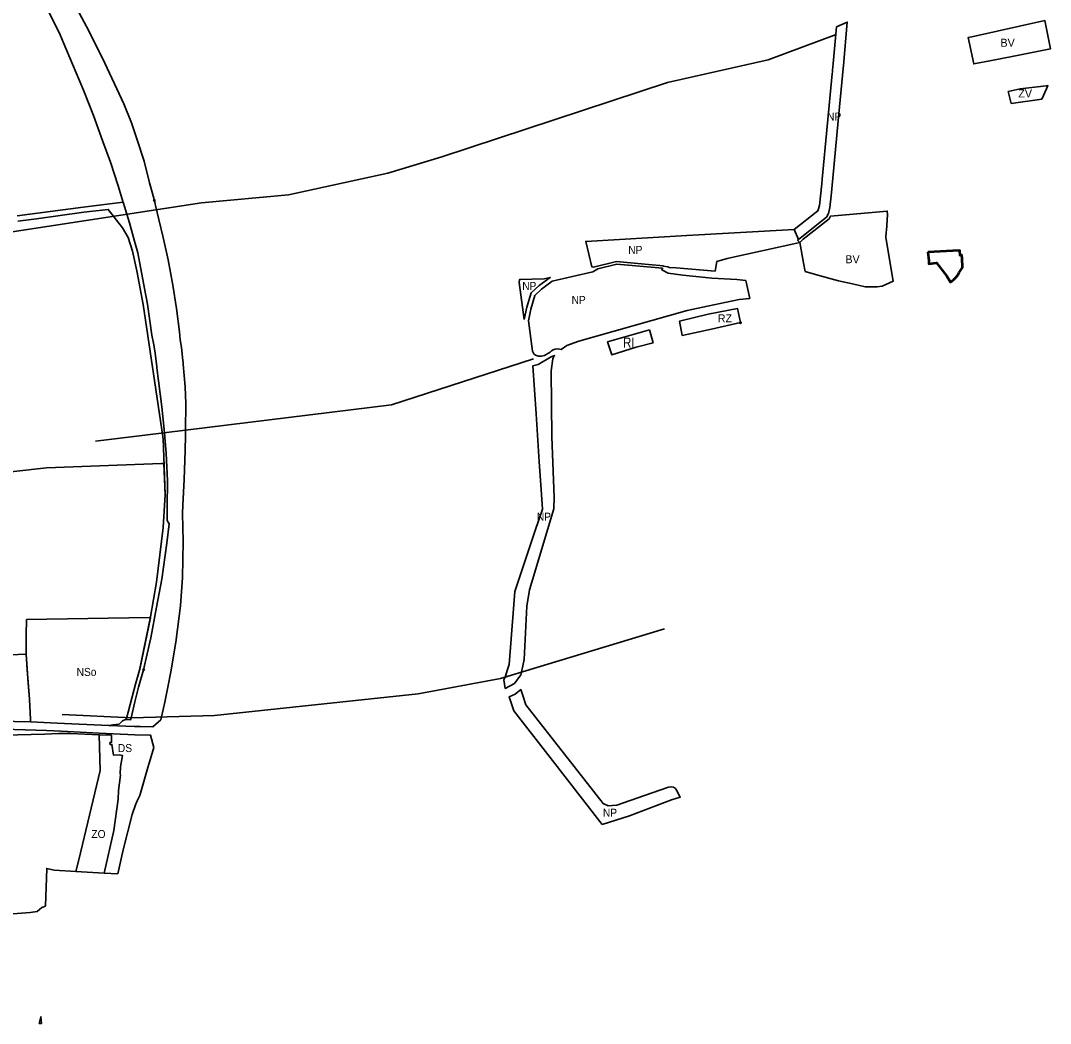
# Model space of a CAD drawing. Extents: x -650276 to -642489, y -1074311 to -1066658.
# Drawn here: x -645218 to -643674, y -1071205 to -1069701 of the extents above; entities that cross this region are included whole.
import ezdxf

# ---------------------------------------------------------------- set-up
doc = ezdxf.new("R2010")
doc.units = 0
doc.header["$LTSCALE"] = 4.8
doc.header["$PDMODE"] = 32
doc.header["$PDSIZE"] = 2.4
for name, color, linetype, lineweight in [('15', 7, 'Continuous', 35), ('24', 7, 'Continuous', 35), ('3', 7, 'Continuous', 35), ('40', 7, 'Continuous', 35), ('42', 7, 'Continuous', 35), ('46', 7, 'Continuous', 35), ('48', 7, 'Continuous', 35), ('54', 7, 'Continuous', 35), ('56', 7, 'Continuous', 35), ('6', 7, 'Continuous', 35), ('60', 7, 'Continuous', 53), ('8', 7, 'Continuous', 35)]:
    doc.layers.add(name, color=color, linetype=linetype, lineweight=lineweight)
doc.layers.add('62', color=7, linetype='Continuous')
doc.layers.add('63', color=7, linetype='Continuous')

msp = doc.modelspace()

# ---------------------------------------------------------------- linework, layer by layer
at = {"layer": '15'}
for points in [[(-645061.76, -1069981.21), (-645064.052, -1069973.429), (-645124.233, -1069980.695), (-645222.809, -1069993.701)], [(-645033.53, -1070674.55), (-645022.64, -1070626.93), (-645014.07, -1070580.72), (-645006.44, -1070538.78), (-644998.92, -1070484.58), (-644995.14, -1070455.72), (-644998.17, -1070450.59), (-644998.25, -1070430.5), (-644997.87, -1070391.16), (-644999.47, -1070349.63), (-645001.64, -1070326.4), (-645001.81, -1070324.58), (-645002.308, -1070319.268), (-645005.98, -1070280.14), (-645013.51, -1070222.04), (-645013.77, -1070220.04), (-645016.92, -1070196.32), (-645018.56, -1070184.92), (-645021.14, -1070173.07), (-645027.49, -1070126.56), (-645032.21, -1070102.73), (-645042.27, -1070049.23), (-645047.28, -1070031.83), (-645054.73, -1070004.56), (-645060.612, -1069985.022), (-645061.76, -1069981.21)], [(-645221.99, -1070001.66), (-645194.003, -1069998.417), (-645123.206, -1069988.629), (-645086.484, -1069984.195), (-645065.235, -1070011.695)], [(-645065.235, -1070011.695), (-645056.555, -1070026.163), (-645050.293, -1070047.035), (-645043.92, -1070076.344), (-645034.122, -1070126.616), (-645004.791, -1070324.889), (-645004.523, -1070326.697)], [(-645004.523, -1070326.697), (-645004.434, -1070327.302), (-645001.312, -1070412.099), (-645004.327, -1070461.264), (-645014.277, -1070543.11), (-645023.048, -1070595.033), (-645039.574, -1070675.065)], [(-645039.574, -1070675.065), (-645045.493, -1070696.321), (-645059.308, -1070747.712), (-645059.403, -1070749.195), (-645053.21, -1070749.75), (-645052.4, -1070746.427), (-645046.63, -1070722.77), (-645041, -1070700.44), (-645033.53, -1070674.55)]]:
    msp.add_lwpolyline(points, dxfattribs=at)
msp.add_point((-645033.53, -1070674.55), dxfattribs=at)
at = {"layer": '24'}
msp.add_line((-645071.18, -1070855.63), (-645071.77, -1070868.73), dxfattribs=at)
for points in [[(-645322.13, -1069447.96), (-645309.62, -1069467.79), (-645303.57, -1069480.49), (-645268.57, -1069533.23), (-645242.75, -1069570.26), (-645230.42, -1069597.39), (-645227.27, -1069602.68), (-645225.7, -1069605.32), (-645214.76, -1069622.37), (-645198.41, -1069650.49), (-645185.17, -1069673.38), (-645179.12, -1069681.3), (-645170.3, -1069698.91), (-645158.43, -1069722.61), (-645153.44, -1069734.71), (-645140.27, -1069766.68), (-645123.84, -1069805.38), (-645108.74, -1069843.58), (-645094.42, -1069882.65), (-645083.31, -1069913.37), (-645071.53, -1069948.89), (-645063.96, -1069973.73), (-645063.23, -1069976.2), (-645062.57, -1069978.46)], [(-645017.46, -1069970.61), (-645018.28, -1069967.49), (-645024.45, -1069944.43), (-645032.85, -1069912.07), (-645043.5, -1069878.37), (-645051.78, -1069854.2), (-645063.26, -1069825.99), (-645095.1, -1069757.62), (-645118.98, -1069710.08), (-645143.56, -1069664.05), (-645148.8, -1069656.1), (-645150.3, -1069653.84), (-645153.33, -1069649.24), (-645166.67, -1069629), (-645184.88, -1069596.58), (-645202.56, -1069568.23), (-645230.1, -1069525.98)], [(-645062.57, -1069978.46), (-645061.76, -1069981.21), (-645060.612, -1069985.022), (-645054.73, -1070004.56), (-645047.28, -1070031.83), (-645042.27, -1070049.23), (-645032.21, -1070102.73), (-645027.49, -1070126.56), (-645021.14, -1070173.07), (-645018.56, -1070184.92), (-645016.92, -1070196.32), (-645013.77, -1070220.04), (-645013.51, -1070222.04), (-645005.98, -1070280.14), (-645002.308, -1070319.268), (-645001.81, -1070324.58), (-645001.64, -1070326.4), (-644999.47, -1070349.63), (-644997.87, -1070391.16), (-644998.25, -1070430.5), (-644998.17, -1070450.59), (-644995.14, -1070455.72), (-644998.92, -1070484.58), (-645006.44, -1070538.78), (-645014.07, -1070580.72), (-645022.64, -1070626.93), (-645033.53, -1070674.55)], [(-644996.88, -1070059.73), (-645004.02, -1070026.44), (-645010.54, -1069999.3), (-645015.548, -1069978.177), (-645016.01, -1069976.23), (-645016.89, -1069972.82), (-645017.46, -1069970.61)], [(-645033.53, -1070674.55), (-645041, -1070700.44), (-645046.63, -1070722.77), (-645052.4, -1070746.427), (-645053.21, -1070749.75), (-645060.46, -1070749.1), (-645065.17, -1070751.39), (-645070.3, -1070755.92), (-645079.38, -1070756.91), (-645085.58, -1070758.04), (-645047.39, -1070759.71), (-645038.44, -1070759.83), (-645019.57, -1070760.07), (-645007.68, -1070749.5), (-645006.739, -1070745.384), (-645001.71, -1070723.39), (-644997.14, -1070700.88), (-644992.6, -1070677.92), (-644985.04, -1070633.43), (-644978.44, -1070578.56), (-644975.05, -1070536.16), (-644974.44, -1070482.48), (-644975.29, -1070440.14), (-644974.69, -1070427.86), (-644972.48, -1070389.15), (-644971.37, -1070345.98), (-644970.61, -1070323.44), (-644970.55, -1070321.56), (-644970.524, -1070315.358), (-644970.36, -1070275.49), (-644971.47, -1070250.14), (-644974, -1070216.2), (-644974.29, -1070213.17), (-644974.49, -1070210.98), (-644976.94, -1070191.41), (-644978.49, -1070180.05), (-644979.57, -1070167.9), (-644984.21, -1070132.81), (-644989.62, -1070097.79), (-644996.88, -1070059.73)], [(-645303, -1070774), (-645182, -1070771), (-645161, -1070770)], [(-645071.99, -1070980.72), (-645064.39, -1070944.7), (-645050.47, -1070891.48), (-645045.74, -1070877.19), (-645043, -1070871.35), (-645039.25, -1070863.33), (-645028.25, -1070824.83), (-645018.18, -1070791.34), (-645023.25, -1070772.62), (-645046.46, -1070771.98), (-645100.32, -1070769.5), (-645156.988, -1070766.884), (-645179.18, -1070765.86), (-645275.8, -1070762.66)], [(-645161, -1070770), (-645143, -1070770), (-645100.268, -1070771.946)], [(-645100.268, -1070771.946), (-645081.75, -1070772.79), (-645081.85, -1070781.59), (-645081.57, -1070783.53)], [(-645081.57, -1070783.53), (-645083.95, -1070783.89), (-645083.49, -1070786.92), (-645081.13, -1070786.56), (-645078.85, -1070802.46), (-645070.2, -1070802.33)], [(-645070.2, -1070802.33), (-645065.01, -1070803.22), (-645068.07, -1070820.37)], [(-645068.07, -1070820.37), (-645068.52, -1070830.52), (-645068.07, -1070832.72), (-645071.18, -1070855.63)], [(-645071.77, -1070868.73), (-645078.23, -1070915.65), (-645092.67, -1070979.52), (-645071.99, -1070980.72)]]:
    msp.add_lwpolyline(points, dxfattribs=at)
for p in [(-645017.46, -1069970.61), (-645033.53, -1070674.55)]:
    msp.add_point(p, dxfattribs=at)
at = {"layer": '3'}
for points in [[(-643791.88, -1069725.25), (-643797.75, -1069726.51), (-643789.3, -1069766.05), (-643786.35, -1069765.46), (-643764.94, -1069761.27), (-643729.34, -1069754.3), (-643674.3, -1069743.53), (-643682.61, -1069701.16)], [(-643920.84, -1070026.46), (-643920.29, -1070017.73), (-643920.16, -1070015.69), (-643918.69, -1069992.23), (-643918.88, -1069986.82), (-644004.06, -1069994.59), (-644005.92, -1069998.62), (-644044.7, -1070029.04), (-644050.12, -1070033.64), (-644044.18, -1070064.43), (-644041.71, -1070077.29), (-644022.77, -1070082.66), (-643991.99, -1070091.37), (-643971.03, -1070095.79), (-643951.99, -1070100.35), (-643933.96, -1070100.18), (-643926.33, -1070099.5), (-643909.87, -1070091.95)]]:
    msp.add_lwpolyline(points, close=True, dxfattribs=at)
at = {"layer": '40'}
for points in [[(-643737.47, -1069807.24), (-643733.02, -1069825.4), (-643687.2, -1069818.8), (-643680.15, -1069803.22), (-643678.02, -1069798.52), (-643680.83, -1069798.86), (-643719.42, -1069803.49)], [(-645442.836, -1070659.455), (-645426.34, -1070660.33), (-645209.41, -1070651.2), (-645206.7, -1070694.76), (-645204.66, -1070718.51), (-645203.13, -1070749.36), (-645202.96, -1070752.89), (-645275.236, -1070750.954), (-645282, -1070742), (-645301, -1070736), (-645324, -1070736), (-645379, -1070743), (-645415, -1070737), (-645435.711, -1070727.497)]]:
    msp.add_lwpolyline(points, close=True, dxfattribs=at)
at = {"layer": '42'}
for points in [[(-645100.268, -1070771.946), (-645098.438, -1070825.558), (-645130.749, -1070959.561), (-645134.972, -1070977.077)], [(-645081.85, -1070781.59), (-645081.75, -1070772.79), (-645100.268, -1070771.946), (-645098.438, -1070825.558), (-645130.749, -1070959.561)], [(-645092.67, -1070979.52), (-645078.23, -1070915.65), (-645071.77, -1070868.73), (-645071.18, -1070855.63), (-645068.07, -1070832.72), (-645068.52, -1070830.52), (-645068.07, -1070820.37), (-645065.01, -1070803.22), (-645070.2, -1070802.33), (-645078.85, -1070802.46), (-645081.13, -1070786.56), (-645081.13, -1070786.56), (-645083.49, -1070786.92), (-645083.95, -1070783.89), (-645081.57, -1070783.53), (-645081.85, -1070781.59), (-645081.75, -1070772.79), (-645100.268, -1070771.946)], [(-645092.67, -1070979.52), (-645078.23, -1070915.65), (-645071.77, -1070868.73), (-645071.18, -1070855.63), (-645068.07, -1070832.72), (-645068.52, -1070830.52), (-645068.07, -1070820.37), (-645065.01, -1070803.22), (-645070.2, -1070802.33), (-645078.85, -1070802.46), (-645081.13, -1070786.56), (-645083.49, -1070786.92)], [(-645083.49, -1070786.92), (-645083.95, -1070783.89), (-645081.57, -1070783.53), (-645081.85, -1070781.59)], [(-645130.749, -1070959.561), (-645134.972, -1070977.077), (-645092.67, -1070979.52)]]:
    msp.add_lwpolyline(points, dxfattribs=at)
msp.add_lwpolyline([(-645186.64, -1071204.86), (-645187.466, -1071194.782), (-645189.902, -1071204.885)], close=True, dxfattribs=at)
msp.add_lwpolyline([(-645186.64, -1071204.86), (-645187.466, -1071194.782), (-645189.902, -1071204.885)], close=True, dxfattribs=at)
at = {"layer": '46'}
for points in [[(-645023.048, -1070595.033), (-645014.277, -1070543.11), (-645004.327, -1070461.264), (-645001.312, -1070412.099), (-645003.03, -1070365.427), (-645003.102, -1070365.432), (-645006.86, -1070365.38), (-645179.26, -1070371.74), (-645326.62, -1070388.32), (-645414.65, -1070395.37), (-645409.38, -1070411.41), (-645408.66, -1070414.62), (-645404.34, -1070433.93), (-645404.4, -1070435.88), (-645440.61, -1070469.53), (-645451.226, -1070466.394), (-645455.09, -1070479.21), (-645458.46, -1070478.86), (-645454.02, -1070501.52), (-645448.36, -1070563), (-645449.82, -1070592.72), (-645442.834, -1070659.455)], [(-645209.41, -1070651.2), (-645209.79, -1070622.69), (-645208.96, -1070599.22)], [(-645208.96, -1070599.22), (-645025.12, -1070596.42), (-645023.346, -1070596.478), (-645023.048, -1070595.033)], [(-645442.834, -1070659.455), (-645426.34, -1070660.33), (-645209.41, -1070651.2)]]:
    msp.add_lwpolyline(points, dxfattribs=at)
at = {"layer": '48'}
for points in [[(-643995.17, -1069710.42), (-643999.94, -1069765.62), (-644000.79, -1069775.42), (-644001.04, -1069778.063), (-644001.29, -1069780.7), (-644016.47, -1069938.99), (-644017.15, -1069945.93), (-644020.26, -1069978.38), (-644022.43, -1069984.87), (-644022.99, -1069986.58), (-644058.55, -1070014.4), (-644051.913, -1070029.549), (-644049.311, -1070027.453), (-644009.95, -1069995.74), (-644006.96, -1069990.34), (-644005.06, -1069981.28), (-644003.06, -1069964.06), (-644000.52, -1069937.19), (-643992.27, -1069851.31), (-643984.845, -1069772.863), (-643984.44, -1069768.58), (-643978.85, -1069703.4), (-643986.744, -1069706.796)], [(-644381.21, -1070181.71), (-644218.65, -1070135.75), (-644188.44, -1070129.43), (-644140.72, -1070119.57), (-644125, -1070117.83), (-644130.91, -1070091.1), (-644144.13, -1070089.47), (-644181.81, -1070087.51), (-644191.26, -1070086.47), (-644225.13, -1070082.95), (-644247.3, -1070079.69), (-644256.54, -1070075.02), (-644255.52, -1070072.5), (-644324.42, -1070066.48), (-644352.71, -1070073.46), (-644360.41, -1070077.91), (-644421.26, -1070091.99), (-644437.34, -1070103.76), (-644447.13, -1070113.11), (-644453.22, -1070133.99), (-644456.41, -1070151.18), (-644450.72, -1070196.97), (-644448.76, -1070200.77), (-644445.9, -1070202.83), (-644441.8, -1070204.26), (-644437.415, -1070204.436), (-644432.53, -1070203.32), (-644424.14, -1070198.29), (-644421.88, -1070196.28), (-644419.51, -1070194.76), (-644416.67, -1070193.7), (-644412.54, -1070193.18), (-644407.55, -1070194.16), (-644399.15, -1070188.55)], [(-644463.28, -1070149.42), (-644459.09, -1070131.08), (-644452.65, -1070109.46), (-644440.64, -1070098.4), (-644423.99, -1070086.17), (-644433.19, -1070088.37), (-644470.17, -1070089.43), (-644470.55, -1070093.61)], [(-644491.691, -1070685.524), (-644491.82, -1070685.92), (-644493.5, -1070689.75), (-644491.42, -1070702.64), (-644477.46, -1070695.09), (-644467.84, -1070682.37), (-644466.998, -1070678.065), (-644463.28, -1070659.06), (-644458.85, -1070579.04), (-644455.2, -1070554.88), (-644418.69, -1070433.36), (-644418.23, -1070415.62), (-644421.45, -1070325.29), (-644422.5, -1070226.42), (-644420.14, -1070208.56), (-644418.61, -1070204.51), (-644417.36, -1070203.24), (-644421.47, -1070204.77), (-644423.66, -1070205.86), (-644442.2, -1070216.72), (-644450.15, -1070219.06), (-644445.28, -1070290.84), (-644440.36, -1070362.62), (-644437.53, -1070404.1), (-644435.51, -1070433.85), (-644447.14, -1070467.28), (-644460.5, -1070507.68), (-644464.98, -1070521.13), (-644476.94, -1070557.45), (-644479.06, -1070583.13), (-644485.64, -1070666.7), (-644488.01, -1070674.2)], [(-644346.21, -1070906.61), (-644305.07, -1070893.39), (-644242.29, -1070869.82), (-644229.12, -1070865.52), (-644234.66, -1070855.08), (-644236.3, -1070852.87), (-644239.47, -1070850.71), (-644243.15, -1070849.89), (-644246.93, -1070850.52), (-644282.77, -1070863.19), (-644324.34, -1070877.71), (-644337.15, -1070878.64), (-644344.86, -1070875.09), (-644460.82, -1070727.21), (-644465.31, -1070713.25), (-644468.1, -1070704.23), (-644476.35, -1070710.99), (-644485.61, -1070714.95), (-644478.67, -1070736.28), (-644424.37, -1070806.03)]]:
    msp.add_lwpolyline(points, close=True, dxfattribs=at)
for points in [[(-644058.55, -1070014.4), (-644219.33, -1070023.53), (-644370.87, -1070032.13), (-644361.74, -1070070.32), (-644359.02, -1070070.67), (-644324.72, -1070062.44), (-644276.85, -1070066.62), (-644254.13, -1070069.08)], [(-644177.01, -1070076.69), (-644177.01, -1070076.69), (-644174.12, -1070062.16), (-644159.02, -1070057.84), (-644050.12, -1070033.64), (-644053.18, -1070030.57), (-644051.913, -1070029.549), (-644058.55, -1070014.4)], [(-644254.13, -1070069.08), (-644254.25, -1070069.37), (-644247.72, -1070070.21), (-644245.9, -1070071.26), (-644235.49, -1070072.08), (-644177.01, -1070076.69)]]:
    msp.add_lwpolyline(points, dxfattribs=at)
at = {"layer": '54'}
for points in [[(-645230.538, -1070017.864), (-644946.741, -1069974.541), (-644816.387, -1069962.572), (-644667.646, -1069930.034), (-644586.303, -1069905.244), (-644248.286, -1069794.155), (-644097.378, -1069760.147), (-643995.653, -1069721.915)], [(-645105.781, -1070331.996), (-645031.648, -1070322.877), (-644662.188, -1070277.428), (-644449.34, -1070208.499)], [(-645155.795, -1070741.501), (-645051.039, -1070746.492), (-644927.167, -1070743.394), (-644622.134, -1070710.86), (-644498.737, -1070687.652), (-644252.543, -1070613.291)]]:
    msp.add_lwpolyline(points, dxfattribs=at)
at = {"layer": '56'}
msp.add_line((-645207.88, -1070674.2), (-645204.66, -1070718.51), dxfattribs=at)
msp.add_lwpolyline([(-645208.96, -1070599.22), (-645209.79, -1070622.69), (-645209.41, -1070651.2), (-645207.88, -1070674.2), (-645204.66, -1070718.51), (-645203.13, -1070749.36), (-645202.96, -1070752.89), (-645163.06, -1070754.64), (-645085.58, -1070758.04), (-645079.38, -1070756.91), (-645070.3, -1070755.92), (-645065.17, -1070751.39), (-645060.46, -1070749.1), (-645059.421, -1070749.039), (-645059.308, -1070747.712), (-645045.493, -1070696.321), (-645039.574, -1070675.065), (-645028.384, -1070620.876), (-645023.346, -1070596.478), (-645025.12, -1070596.42)], close=True, dxfattribs=at)
for points in [[(-645208.96, -1070599.22), (-645209.79, -1070622.69), (-645209.41, -1070651.2), (-645207.88, -1070674.2)], [(-645023.346, -1070596.478), (-645025.12, -1070596.42), (-645208.96, -1070599.22)], [(-645060.46, -1070749.1), (-645059.421, -1070749.039), (-645059.308, -1070747.712), (-645045.493, -1070696.321), (-645039.574, -1070675.065), (-645039.338, -1070673.923), (-645023.346, -1070596.478)], [(-645204.66, -1070718.51), (-645203.13, -1070749.36), (-645202.96, -1070752.89)], [(-645202.96, -1070752.89), (-645163.06, -1070754.64), (-645085.58, -1070758.04), (-645079.38, -1070756.91), (-645070.3, -1070755.92), (-645065.17, -1070751.39), (-645060.46, -1070749.1)], [(-645100.268, -1070771.946), (-645143, -1070770), (-645161, -1070770), (-645182, -1070771), (-645303, -1070774), (-645351, -1070800), (-645400.05, -1070819.84), (-645406.09, -1070822.34), (-645409.52, -1070823.76), (-645418.67, -1070827.72), (-645421.09, -1070827.89), (-645433.49, -1070828.76), (-645452.31, -1070825.52), (-645455.184, -1070825.042)], [(-645130.749, -1070959.561), (-645098.438, -1070825.558), (-645100.268, -1070771.946)], [(-645495.87, -1071017.81), (-645475.01, -1071020.72), (-645426.38, -1071032.8), (-645361.54, -1071041.54), (-645255.93, -1071042.36), (-645203.66, -1071038.81), (-645193.24, -1071037.31), (-645186.18, -1071030.83), (-645180.72, -1071028.86), (-645178.73, -1070972.35), (-645167.47, -1070975.2), (-645134.973, -1070977.077), (-645134.973, -1070977.077), (-645130.749, -1070959.561)]]:
    msp.add_lwpolyline(points, dxfattribs=at)
at = {"layer": '6'}
msp.add_lwpolyline([(-644275.05, -1070164.59), (-644338.06, -1070182.64), (-644331.9, -1070202.4), (-644295.01, -1070190.9), (-644269.84, -1070184.57)], close=True, dxfattribs=at)
at = {"layer": '60'}
msp.add_lwpolyline([(-643858.23, -1070048.35), (-643856.72, -1070061.26), (-643856.49, -1070065.66), (-643844.87, -1070064.51), (-643829.38, -1070084.37), (-643824.22, -1070093.34), (-643819.67, -1070089.82), (-643815.9, -1070086.27), (-643813.21, -1070082.8), (-643810.91, -1070078.63), (-643806.17, -1070071.18), (-643806.59, -1070057.37), (-643806.86, -1070053.03), (-643809.71, -1070053.15), (-643810, -1070046), (-643820.78, -1070046.59)], close=True, dxfattribs=at)
at = {"layer": '8'}
for p, q in [((-644138.78, -1070154.07), (-644143.31, -1070132.95)), ((-644182.31, -1070163.66), (-644138.78, -1070154.07))]:
    msp.add_line(p, q, dxfattribs=at)
msp.add_lwpolyline([(-644143.31, -1070132.95), (-644143.31, -1070132.95), (-644143.31, -1070132.95), (-644187.11, -1070141.58), (-644230.4, -1070152.08), (-644226.23, -1070173.28), (-644182.31, -1070163.66)], dxfattribs=at)
msp.add_point((-644138.78, -1070154.07), dxfattribs=at)

# ---------------------------------------------------------------- texts
at = {"layer": '62'}
for s, p in [('BV', (-643749.135, -1069740.303)), ('ZV', (-643722.385, -1069816.315)), ('BV', (-643981.639, -1070065.037)), ('RZ', (-644172.882, -1070153.612))]:
    msp.add_text(s, height=12, dxfattribs=at).set_placement(p)
for s, height, width, p in [('NP', 12, 0.95, (-644008.985, -1069850.967)), ('NP', 12, 0.95, (-644306.985, -1070050.967)), ('NP', 12, 0.95, (-644465.985, -1070104.967)), ('NP', 12, 0.95, (-644391.985, -1070125.967)), ('RI', 15, 0.85, (-644314.705, -1070191.481)), ('NP', 12, 0.95, (-644444, -1070450.967)), ('DS', 12, 0.95, (-645072.003, -1070798.001)), ('NP', 12, 0.95, (-644345, -1070894.967)), ('ZO', 12, 0.95, (-645111.758, -1070926.853))]:
    msp.add_text(s, height=height, dxfattribs=dict(at, width=width)).set_placement(p)
at = {"layer": '63', "width": 0.95}
msp.add_text('NSo', height=12, dxfattribs=at).set_placement((-645133.866, -1070683.823))

doc.saveas('drawing.dxf')
